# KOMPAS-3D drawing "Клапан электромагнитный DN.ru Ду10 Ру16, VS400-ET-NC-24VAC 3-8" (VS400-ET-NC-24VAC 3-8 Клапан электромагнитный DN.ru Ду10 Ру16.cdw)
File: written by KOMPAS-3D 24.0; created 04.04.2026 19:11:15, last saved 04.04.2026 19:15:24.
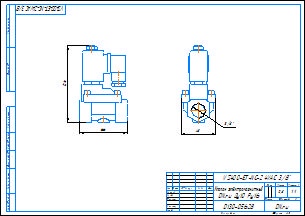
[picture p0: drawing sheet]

Document properties: c3d_UniqueCompID: ef56311e-7521-43dc-8291-0e6108b3d81d; Обозначение: VS400-ET-NC-220VAC 3-8; Наименование: Клапан электромагнитный DN.ru Ду10 Ру16; Автор: artio; Класс точности: c; Знак неуказанной шероховатости: Шероховатость не задана; Рассекать на разрезах: Да; Автор: artio; Форматы листов документа: A3; Полное имя файла: VS400-ET-NC-24VAC 3-8 Клапан электромагнитный DN.ru Ду10 Ру16.m3d; Масса: 0.797; Наименование: Клапан электромагнитный DN.ru Ду10 Ру16; Количество листов документа: 1; Примечание: D130-05628

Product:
- Body: Тело 1  | qty 1
    Масса: 1.030062
- Part/product: Клапан электромагнитный DN.ru Ду10 Ру16  | designation VS400-ET-NC-24VAC 3-8
    Масса: 0.797
    Раздел спецификации: Прочие изделия
    Примечание: D130-05628
    additional columns: ef56311e-7521-43dc-8291-0e6108b3d81d; VS400-ET-NC-220VAC 3-8; artio; c; Шероховатость не задана; Да

Views: Вид 1, Спереди, Проекционный вид 2
Referenced files in C:\Users\artio\OneDrive\Рабочий стол\Клапан электромагнитный DN.ru\VS400-ET-NC\VS400-ET-NC-24VDC\: VS400-ET-NC-24VDC 3-8 Клапан электромагнитный DN.ru Ду10 Ру16.m3d
Referenced files in C:\Users\artio\OneDrive\Рабочий стол\Клапан электромагнитный DN.ru\VS400-ET-NC\VS400-ET-NC-24VAC\: VS400-ET-NC-24VAC 3-8 Клапан электромагнитный DN.ru Ду10 Ру16.m3d
Referenced files in C:\Users\artio\OneDrive\Рабочий стол\Клапан электромагнитный DN.ru\VS400-ET-NC\: VS400-ET-NC-24VDC 3-8 Клапан электромагнитный DN.ru Ду10 Ру16.cdw
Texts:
  VS400-ET-NC-24VAC 3-8
  Клапан электромагнитный
  DN.ru Ду10 Ру16
  VS400-ET-NC-24VAC 3/8"
  VS400-ET-NC-24VAC 3/8"-
  Клапан электромагнитный DN.ru Ду10 Ру16
  VS400-ET-NC-24VAC 3-8 Клапан электромагнитный DN.ru Ду10 Ру16
Dimensions and other numbers on the sheet: 0; 3; 2; 4; 48; 3/8"; 66; 106; 1:1; 1; 0,8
